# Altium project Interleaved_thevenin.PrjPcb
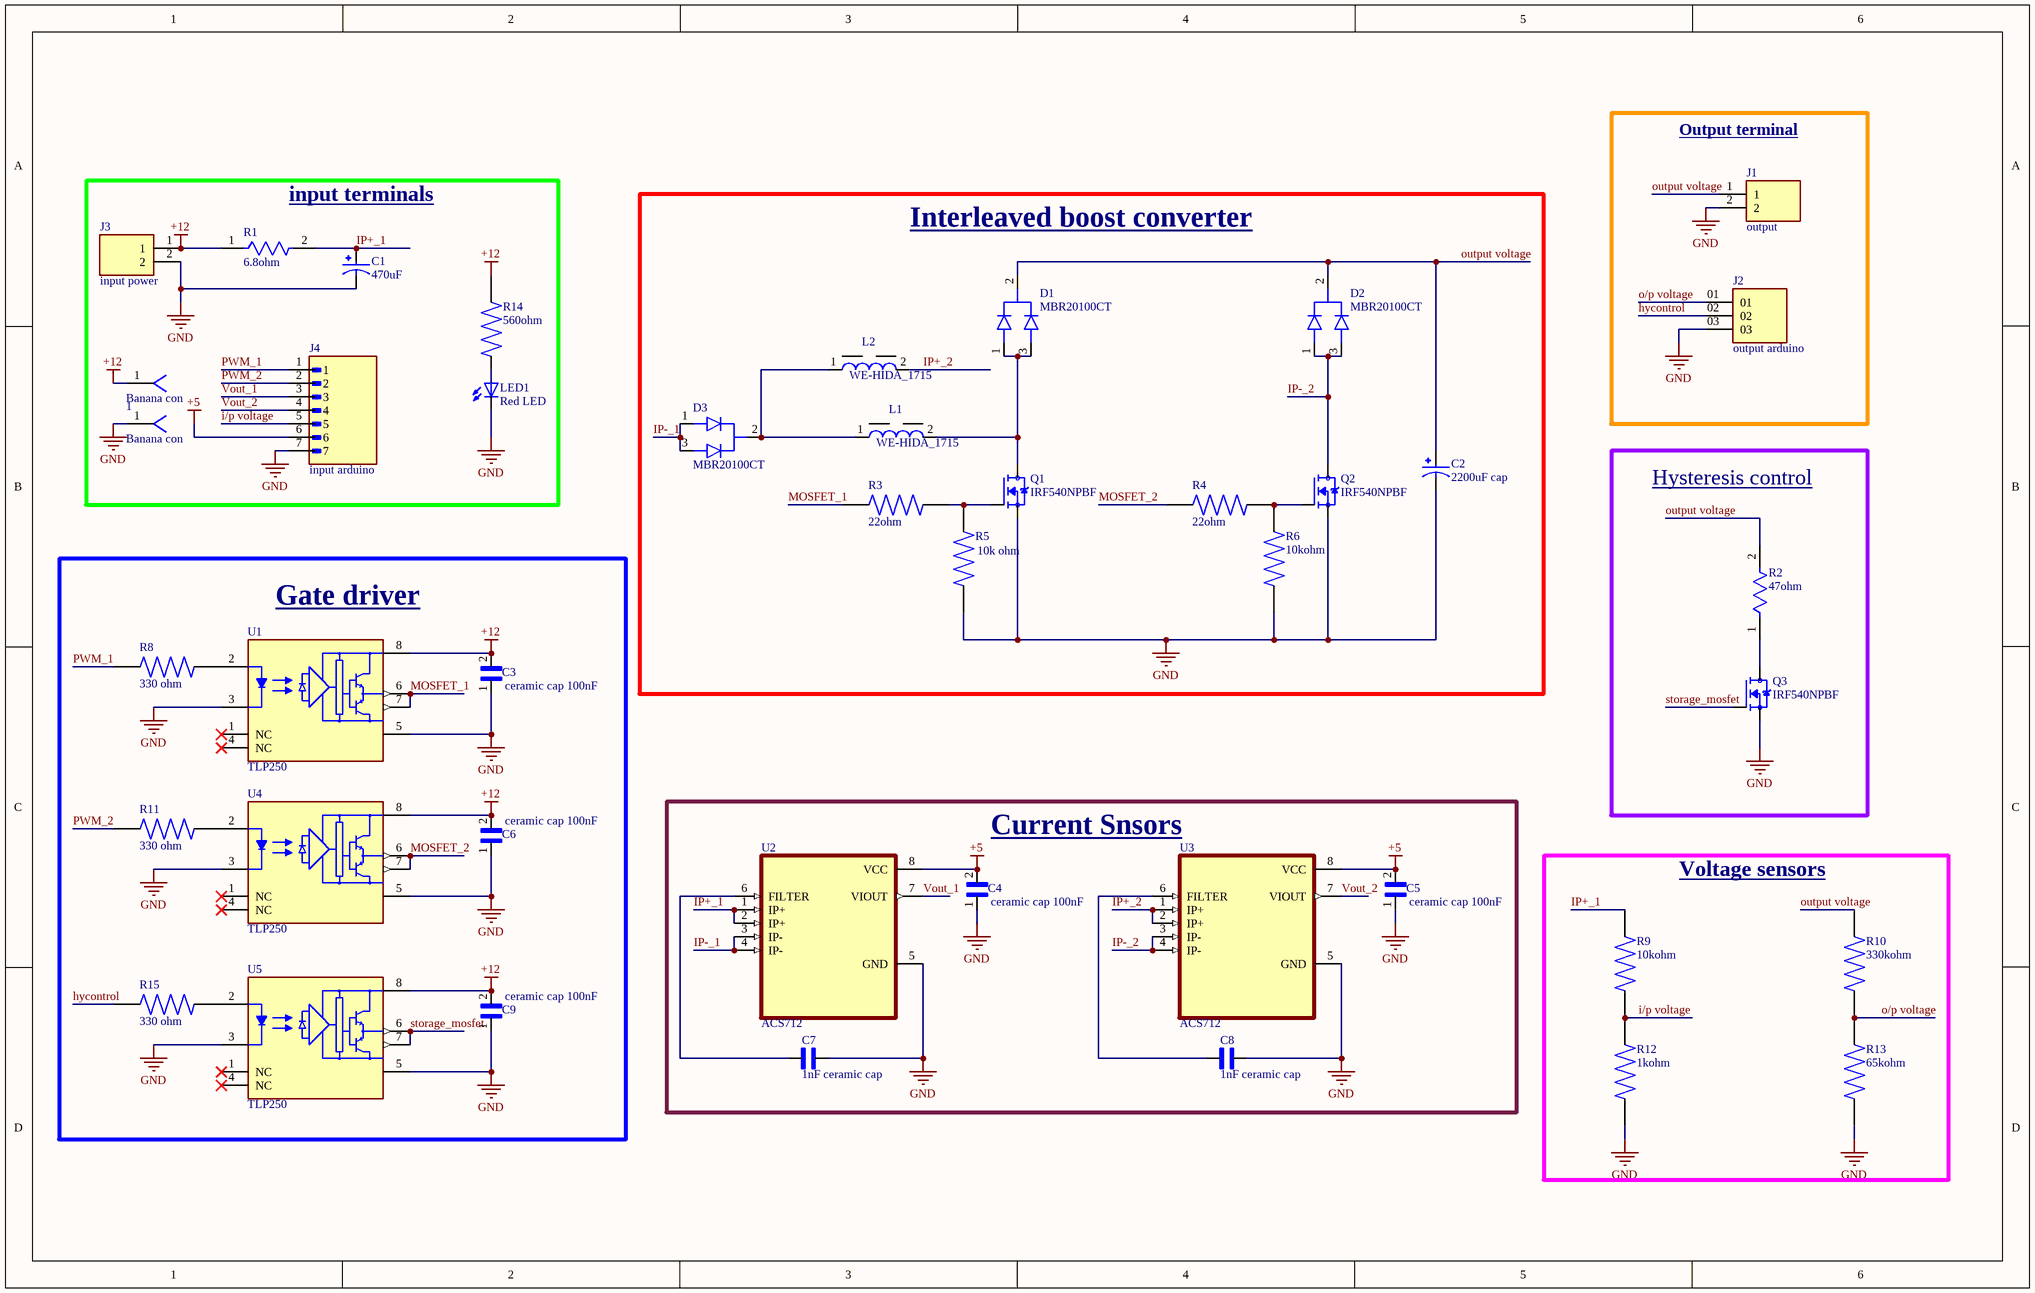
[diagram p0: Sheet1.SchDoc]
1 sheet, 43 parts. Net scope: global (net labels, ports and power ports of the same name join across sheets).
Board file: interleaved_thevenin.PcbDoc

## Sheet Sheet1.SchDoc
size 381 x 241 mm; SheetNumber: 1; SheetTotal: 1

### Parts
1  Banana con  [KEYSTONE_575-4]
C1  470uF  [470uF]
C2  2200uF cap  [2200uF cap]
C3  ceramic cap 100nF  [ceramic cap 100nF]
C4  ceramic cap 100nF  [ceramic cap 100nF]
C5  ceramic cap 100nF  [ceramic cap 100nF]
C6  ceramic cap 100nF  [ceramic cap 100nF]
C7  1nF ceramic cap  [1nF ceramic cap]
C8  1nF ceramic cap  [1nF ceramic cap]
C9  ceramic cap 100nF  [ceramic cap 100nF]
D1  MBR20100CT  [TO254P1066X482X2286-3]
D2  MBR20100CT  [TO254P1066X482X2286-3]
D3  MBR20100CT  [TO254P1066X482X2286-3]
J1  output  [terminal block]
J2  output arduino  [3 male pins header]
J3  input power  [terminal block]
J4  input arduino  [7 male pin header]
L1  WE-HIDA_1715  [2mH inductor]
L2  WE-HIDA_1715  [2mH inductor]
LED1  Red LED  [Red LED]
Q1  IRF540NPBF  [TO254P1054X469X1930-3]
Q2  IRF540NPBF  [TO254P1054X469X1930-3]
Q3  IRF540NPBF  [TO254P1054X469X1930-3]
R1  6.8ohm  [5W power resistor]
R2  47ohm  [5W power resistor]
R3  22ohm  [TH resistor]
R4  22ohm  [TH resistor]
R5  10k ohm  [TH resistor]
R6  10kohm  [TH resistor]
R8  330 ohm  [TH resistor]
R9  10kohm  [TH resistor]
R10  330kohm  [TH resistor]
R11  330 ohm  [TH resistor]
R12  1kohm  [TH resistor]
R13  65kohm  [TH resistor]
R14  560ohm  [TH resistor]
R15  330 ohm  [TH resistor]
U1  TLP250  [DIP762W50P254L966H485Q8]
U2  ACS712  [ACS712]
U3  ACS712  [ACS712]
U4  TLP250  [DIP762W50P254L966H485Q8]
U5  TLP250  [DIP762W50P254L966H485Q8]
  Banana con  [KEYSTONE_575-4]

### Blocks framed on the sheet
Output terminal: J1 J2
input terminals: 1 C1 J3 J4 LED1 R1 R14 
Interleaved boost converter: C2 D1-D3 L1 L2 Q1 Q2 R3-R6
Hysteresis control: Q3 R2
Gate driver: C3 C6 C9 R8 R11 R15 U1 U4 U5
Current Snsors: C4 C5 C7 C8 U2 U3
Voltage sensors: R9 R10 R12 R13

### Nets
+5: C4.2 C5.2 J4.6 U2.8(VCC) U3.8(VCC)
+12: C3.2 C6.2 C9.2 J3.1 R1.1 R14.2 U1.8(VCC) U4.8(VCC) U5.8(VCC) .1
GND: 1.1 C1.N C2.N C3.1 C4.1 C5.1 C6.1 C7.2 C8.2 C9.1 J1.2 J2.03 J3.2 J4.7 LED1.K(C) Q1.3(S) Q2.3(S) Q3.3(S) R5.1 R6.1 R12.1 R13.1 U1.3(CATHODE) U1.5(GND) U2.5(GND) U3.5(GND) U4.3(CATHODE) U4.5(GND) U5.3(CATHODE) U5.5(GND)
hycontrol: J2.02 R15.1
i/p voltage: J4.5 R9.1 R12.2
IP+_1: C1.P R1.2 R9.2 U2.1(IP+) U2.2(IP+)
IP+_2: L2.2 U3.1(IP+) U3.2(IP+)
IP-_1: D3.1(ANODE1) D3.3(ANODE2) U2.3(IP-) U2.4(IP-)
IP-_2: D2.1(ANODE1) D2.3(ANODE2) Q2.2(D) U3.3(IP-) U3.4(IP-)
MOSFET_1: R3.1 U1.6(VO) U1.7(VO)
MOSFET_2: R4.1 U4.6(VO) U4.7(VO)
o/p voltage: J2.01 R10.1 R13.2
output voltage: C2.P D1.2(COMMON_CATHODE) D2.2(COMMON_CATHODE) J1.1 R2.2 R10.2
PWM_1: J4.1 R8.1
PWM_2: J4.2 R11.1
storage_mosfet: Q3.1(G) U5.6(VO) U5.7(VO)
Vout_1: J4.3 U2.7(VIOUT)
Vout_2: J4.4 U3.7(VIOUT)
NetC7_1: C7.1 U2.6(FILTER)
NetC8_1: C8.1 U3.6(FILTER)
NetD1_1: D1.1(ANODE1) D1.3(ANODE2) L1.2 Q1.2(D)
NetD3_2: D3.2(COMMON_CATHODE) L1.1 L2.1
NetLED1_A: LED1.A R14.1
NetQ1_1: Q1.1(G) R3.2 R5.2
NetQ2_1: Q2.1(G) R4.2 R6.2
NetQ3_2: Q3.2(D) R2.1
NetR8_2: R8.2 U1.2(ANODE)
NetR11_2: R11.2 U4.2(ANODE)
NetR15_2: R15.2 U5.2(ANODE)

Not connected (* = marked no-connect by the designer): U1 1(NC)* 4(NC)*; U4 1(NC)* 4(NC)*; U5 1(NC)* 4(NC)*

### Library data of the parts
1  = Banana con: Battery Holders, Contacts and Clips JACK; MF: {'manufacturer': u'Keystone Electronics'}; MP: 575-4
C1 = 470uF: 470ÂµF 25V Aluminum Electrolytic Capacitors Radial, Can 2000 Hrs @ 105Â°C; MF: Panasonic; MP: EEUHD1E471
C2 = 2200uF cap: CAP ALUM 2200UF 20% 35V RADIAL; MF: Panasonic; MP: EEU-HD1V222
C3-C6 C9 = ceramic cap 100nF: AR 100nF Ceramic Multilayer Cap,50V dc,+125C,X7R Dielectric,+/-10%,Through Hole ¦ AVX AR215C104K4R
C7 C8 = 1nF ceramic cap: SR Series 5.08 x 5.08 mm 1 nF 100 V Â±5% Tolerance C0G/NP0 Radial Lead/SkyCapÂ®; MF: AVX; MP: SR201A102JARTR1
D1-D3 = MBR20100CT: 20A, 100V, Planar Schottky; MF: Taiwan Semiconductor
J1 J3 = terminal block: MP: OSTTA020161
J2 = 3 male pins header: MF: Samtec; MP: HTSW-103-XX-X-S
J4 = 7 male pin header: MP: M20-9770746
L1 L2 = 2mH E shape
LED1 = Red LED: Red 619nm LED Indication - Discrete 1.9V Radial; MF: Vishay; MP: TLLR4400
Q1-Q3 = IRF540NPBF: RoHS Compliant ¦ Low RDS(on) ¦ Industry-leading quality ¦ Dynamic dv/dt Rating ¦ Fast Switching ¦ Fully Avalanche Rated ¦ 175C Operating Temperature; MF: Infineon
R1 R2 = 5W power resistor: CAW54R70JLF Thick Film Resistors - Through Hole 4.7 OHM 5% 5W; NexarPartId: 5426963; Voltage Rating: 350V; Temperature Coefficient: 400ppm/°C; Resistance: 4.7Ω
R3-R6 R8-R15 = TH resistor: 1.07 kOhms Â±1% 0.25W, 1/4W Through Hole Resistor Axial - Metal Film; MF: Yageo; MP: MFR-25FBF52-1K
U1 U4 U5 = TLP250: Logic Output Optoisolator - Push-Pull, Totem Pole 3750Vrms 1 Channel 40kV/Âµs CMTI 8-SMD; MF: Toshiba Semiconductor
U2 U3 = ACS712: Fully Integrated, Hall-Effect-Based Linear Current Sensor IC with 2.4 kVRMS Isolation and a Low-Resistance Current Conductor; MF: Allegro; MP: ACS712ELCTR-20A-S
